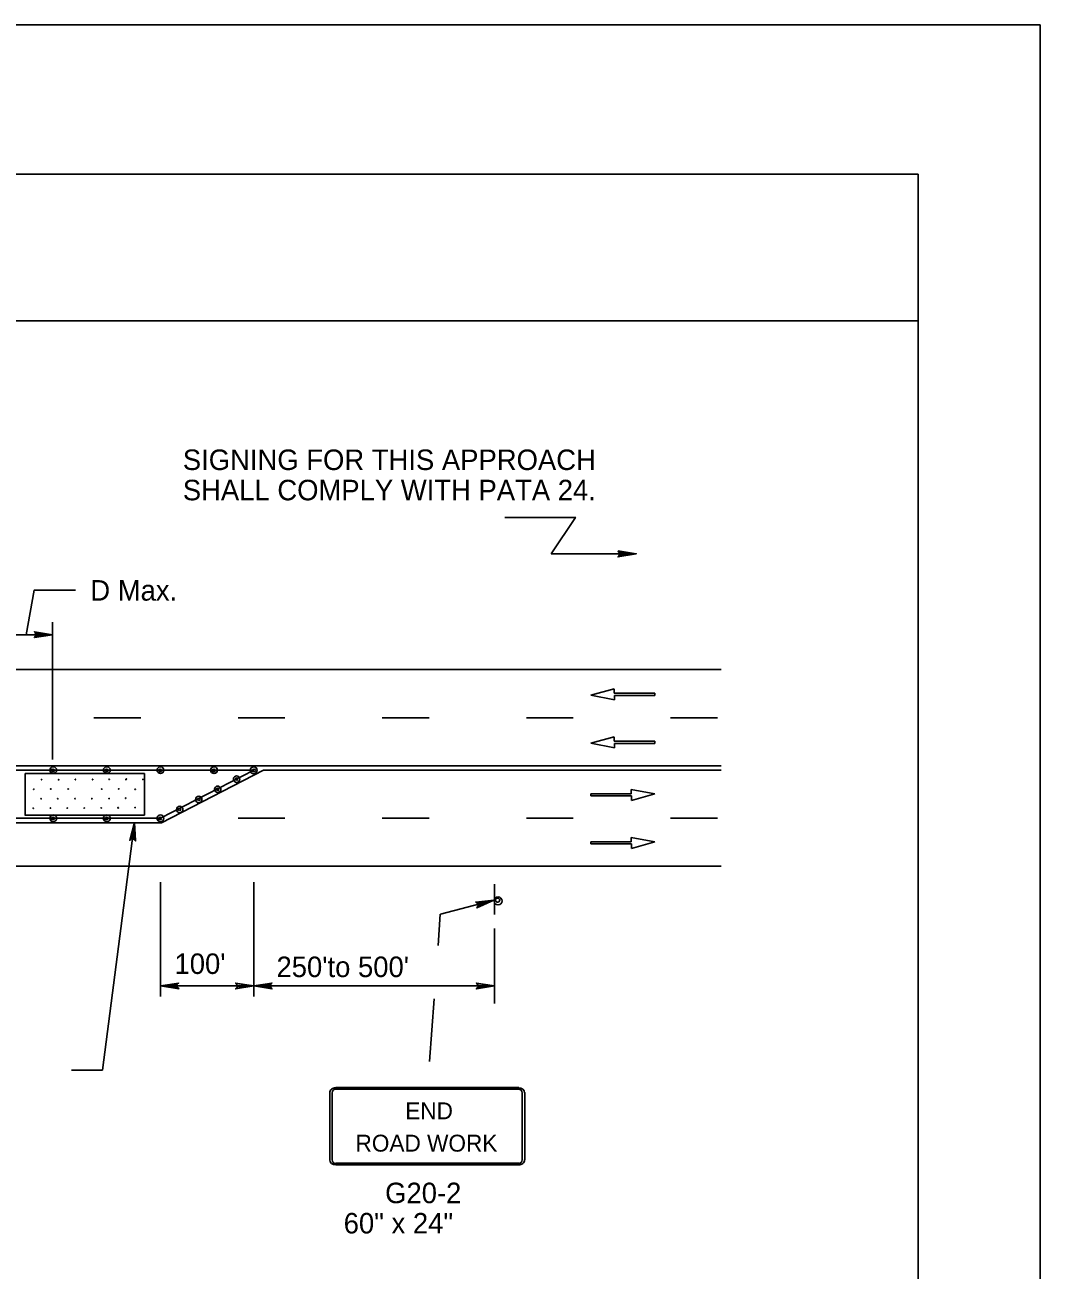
# Model space of a CAD drawing. Extents: x -14145 to -13521, y 30244 to 30661.
# Drawn here: x -13767.57 to -13757.17, y 30329.56 to 30342.31 of the extents above; entities that cross this region are included whole.
import ezdxf

# ---------------------------------------------------------------- set-up
doc = ezdxf.new("R2010")
doc.units = 0
for name, color, linetype in [('1', 7, 'Continuous'), ('10', 7, 'Continuous'), ('2', 7, 'Continuous'), ('61', 7, 'Continuous')]:
    doc.layers.add(name, color=color, linetype=linetype)

msp = doc.modelspace()

# ---------------------------------------------------------------- linework, layer by layer
at = {"layer": '1'}
for p, q in [((-13762.654, 30337.264), (-13761.928, 30337.264)), ((-13761.929, 30337.263), (-13762.18, 30336.89)), ((-13762.18, 30336.89), (-13761.309, 30336.89)), ((-13767.284, 30334.784), (-13767.284, 30336.19)), ((-13767.825, 30336.063), (-13767.283, 30336.063)), ((-13787.525, 30335.705), (-13760.437, 30335.705)), ((-13761.533, 30335.509), (-13761.774, 30335.443)), ((-13761.774, 30335.443), (-13761.53, 30335.397)), ((-13761.533, 30335.464), (-13761.533, 30335.509)), ((-13761.117, 30335.464), (-13761.533, 30335.464)), ((-13761.53, 30335.397), (-13761.53, 30335.442)), ((-13761.53, 30335.442), (-13761.117, 30335.442)), ((-13761.117, 30335.442), (-13761.117, 30335.464)), ((-13766.381, 30335.213), (-13766.861, 30335.213)), ((-13764.905, 30335.213), (-13765.385, 30335.213)), ((-13763.429, 30335.213), (-13763.909, 30335.213)), ((-13761.953, 30335.213), (-13762.433, 30335.213)), ((-13760.477, 30335.213), (-13760.957, 30335.213)), ((-13761.533, 30335.017), (-13761.774, 30334.951)), ((-13761.774, 30334.951), (-13761.53, 30334.905)), ((-13761.533, 30334.972), (-13761.533, 30335.017)), ((-13761.117, 30334.972), (-13761.533, 30334.972)), ((-13761.53, 30334.905), (-13761.53, 30334.95)), ((-13761.53, 30334.95), (-13761.117, 30334.95)), ((-13761.117, 30334.95), (-13761.117, 30334.972)), ((-13787.525, 30334.721), (-13760.437, 30334.721)), ((-13772.345, 30334.676), (-13765.224, 30334.676)), ((-13766.179, 30334.183), (-13765.224, 30334.675)), ((-13766.168, 30334.138), (-13765.125, 30334.676)), ((-13765.125, 30334.676), (-13760.438, 30334.676)), ((-13766.341, 30334.641), (-13767.565, 30334.641)), ((-13767.565, 30334.215), (-13767.565, 30334.641)), ((-13766.341, 30334.215), (-13766.341, 30334.641)), ((-13761.36, 30334.434), (-13761.774, 30334.434)), ((-13761.774, 30334.434), (-13761.774, 30334.412)), ((-13761.117, 30334.433), (-13761.36, 30334.479)), ((-13761.36, 30334.479), (-13761.36, 30334.434)), ((-13761.358, 30334.366), (-13761.117, 30334.433)), ((-13761.774, 30334.412), (-13761.358, 30334.412)), ((-13761.358, 30334.412), (-13761.358, 30334.366)), ((-13770.022, 30334.183), (-13766.179, 30334.183)), ((-13767.566, 30334.215), (-13766.342, 30334.215)), ((-13764.905, 30334.184), (-13765.385, 30334.184)), ((-13763.429, 30334.184), (-13763.909, 30334.184)), ((-13761.953, 30334.184), (-13762.433, 30334.184)), ((-13760.477, 30334.184), (-13760.957, 30334.184)), ((-13770.022, 30334.138), (-13766.168, 30334.138)), ((-13766.445, 30334.138), (-13766.773, 30331.604)), ((-13761.36, 30333.942), (-13761.774, 30333.942)), ((-13761.774, 30333.942), (-13761.774, 30333.92)), ((-13761.774, 30333.92), (-13761.358, 30333.92)), ((-13761.117, 30333.941), (-13761.36, 30333.987)), ((-13761.36, 30333.987), (-13761.36, 30333.942)), ((-13761.358, 30333.874), (-13761.117, 30333.941)), ((-13761.358, 30333.92), (-13761.358, 30333.874)), ((-13787.525, 30333.692), (-13760.437, 30333.692)), ((-13766.178, 30332.357), (-13766.178, 30333.529)), ((-13765.224, 30332.357), (-13765.224, 30333.529)), ((-13762.759, 30333.51), (-13762.759, 30333.198)), ((-13762.759, 30333.51), (-13762.759, 30333.198)), ((-13763.312, 30333.203), (-13762.765, 30333.343)), ((-13763.337, 30332.881), (-13763.314, 30333.203)), ((-13762.76, 30333.053), (-13762.76, 30332.285)), ((-13766.178, 30332.466), (-13765.224, 30332.466)), ((-13762.759, 30332.466), (-13765.224, 30332.466)), ((-13763.425, 30331.693), (-13763.377, 30332.336)), ((-13766.773, 30331.604), (-13767.09, 30331.604)), ((-13764.445, 30331.375), (-13764.445, 30330.687)), ((-13764.42, 30331.375), (-13764.42, 30330.687)), ((-13762.511, 30331.426), (-13764.384, 30331.426)), ((-13762.511, 30331.426), (-13764.384, 30331.426)), ((-13762.511, 30331.411), (-13764.384, 30331.411)), ((-13762.511, 30331.411), (-13764.384, 30331.411)), ((-13762.475, 30330.687), (-13762.475, 30331.375)), ((-13762.45, 30330.687), (-13762.45, 30331.375)), ((-13764.384, 30330.65), (-13762.511, 30330.65)), ((-13764.384, 30330.635), (-13762.511, 30330.635))]:
    msp.add_line(p, q, dxfattribs=at)
for points in [[(-13761.488, 30336.913), (-13761.48, 30336.899), (-13761.308, 30336.891), (-13761.488, 30336.913), (-13761.493, 30336.92), (-13761.308, 30336.891), (-13761.479, 30336.879), (-13761.487, 30336.869), (-13761.308, 30336.891), (-13761.496, 30336.859), (-13761.487, 30336.869)], [(-13767.049, 30336.519), (-13767.471, 30336.519), (-13767.554, 30336.063)], [(-13767.463, 30336.087), (-13767.457, 30336.075), (-13767.283, 30336.063), (-13767.463, 30336.087), (-13767.469, 30336.093), (-13767.283, 30336.063), (-13767.457, 30336.057), (-13767.463, 30336.045), (-13767.283, 30336.063), (-13767.469, 30336.033), (-13767.463, 30336.045)], [(-13766.487, 30333.969), (-13766.474, 30333.973), (-13766.444, 30334.139), (-13766.487, 30333.969), (-13766.494, 30333.957), (-13766.444, 30334.139), (-13766.457, 30333.971), (-13766.445, 30333.963), (-13766.444, 30334.139), (-13766.434, 30333.951), (-13766.445, 30333.963)], [(-13762.945, 30333.319), (-13762.933, 30333.307), (-13762.765, 30333.343), (-13762.945, 30333.319), (-13762.951, 30333.325), (-13762.765, 30333.343), (-13762.927, 30333.289), (-13762.933, 30333.277), (-13762.765, 30333.343), (-13762.939, 30333.265), (-13762.933, 30333.277)], [(-13765.998, 30332.448), (-13766.01, 30332.46), (-13766.178, 30332.466), (-13765.998, 30332.448), (-13765.992, 30332.436), (-13766.178, 30332.466), (-13766.01, 30332.478), (-13766.004, 30332.49), (-13766.178, 30332.466), (-13765.992, 30332.496), (-13766.004, 30332.49)], [(-13765.404, 30332.49), (-13765.392, 30332.472), (-13765.224, 30332.466), (-13765.404, 30332.49), (-13765.41, 30332.496), (-13765.224, 30332.466), (-13765.392, 30332.46), (-13765.398, 30332.442), (-13765.224, 30332.466), (-13765.41, 30332.436), (-13765.398, 30332.442)], [(-13765.044, 30332.448), (-13765.05, 30332.46), (-13765.224, 30332.466), (-13765.044, 30332.448), (-13765.038, 30332.436), (-13765.224, 30332.466), (-13765.05, 30332.478), (-13765.044, 30332.49), (-13765.224, 30332.466), (-13765.038, 30332.496), (-13765.044, 30332.49)], [(-13762.939, 30332.49), (-13762.927, 30332.472), (-13762.759, 30332.466), (-13762.939, 30332.49), (-13762.945, 30332.496), (-13762.759, 30332.466), (-13762.927, 30332.454), (-13762.939, 30332.442), (-13762.759, 30332.466), (-13762.945, 30332.436), (-13762.939, 30332.442)]]:
    msp.add_lwpolyline(points, dxfattribs=at)
for centre, radius in [((-13767.277, 30334.676), 0.0354), ((-13767.28, 30334.673), 0.0143), ((-13766.728, 30334.676), 0.0354), ((-13766.731, 30334.673), 0.0143), ((-13766.179, 30334.676), 0.0354), ((-13766.182, 30334.673), 0.0143), ((-13765.63, 30334.676), 0.0354), ((-13765.633, 30334.673), 0.0143), ((-13765.224, 30334.675), 0.0354), ((-13765.221, 30334.672), 0.0143), ((-13767.396, 30334.579), 0.00272), ((-13767.221, 30334.578), 0.00272), ((-13767.049, 30334.58), 0.00272), ((-13766.874, 30334.58), 0.00272), ((-13766.703, 30334.582), 0.00272), ((-13766.532, 30334.58), 0.00272), ((-13766.528, 30334.585), 0.00272), ((-13766.358, 30334.581), 0.00272), ((-13765.399, 30334.583), 0.0331), ((-13765.398, 30334.584), 0.012), ((-13767.476, 30334.481), 0.00272), ((-13767.301, 30334.483), 0.00272), ((-13767.123, 30334.483), 0.00272), ((-13766.78, 30334.482), 0.00272), ((-13766.606, 30334.484), 0.00272), ((-13766.438, 30334.481), 0.00272), ((-13765.593, 30334.48), 0.0331), ((-13765.592, 30334.481), 0.012), ((-13767.401, 30334.383), 0.00272), ((-13767.23, 30334.383), 0.00272), ((-13767.053, 30334.384), 0.00272), ((-13766.959, 30334.288), 0.00272), ((-13766.88, 30334.384), 0.00272), ((-13766.785, 30334.289), 0.00272), ((-13766.705, 30334.385), 0.00272), ((-13766.613, 30334.292), 0.00272), ((-13766.612, 30334.289), 0.00272), ((-13766.534, 30334.389), 0.00272), ((-13766.439, 30334.293), 0.00272), ((-13765.982, 30334.273), 0.0331), ((-13765.787, 30334.376), 0.0331), ((-13765.786, 30334.377), 0.012), ((-13767.481, 30334.286), 0.00272), ((-13767.277, 30334.183), 0.0354), ((-13767.306, 30334.287), 0.00272), ((-13767.28, 30334.18), 0.0143), ((-13767.133, 30334.287), 0.00272), ((-13766.728, 30334.183), 0.0354), ((-13766.731, 30334.18), 0.0143), ((-13766.179, 30334.183), 0.0354), ((-13766.182, 30334.18), 0.0143), ((-13765.981, 30334.274), 0.012), ((-13762.722, 30333.337), 0.0408)]:
    msp.add_circle(centre, radius, dxfattribs=at)
msp.add_arc((-13762.727, 30333.345), 0.0214, 189.521, 184.2501, dxfattribs=at)
for centre, major_axis, ratio, start_param, end_param in [((-13764.385, 30331.373), (0.0609, 0), 0.839899, 1.570796, 3.141593), ((-13764.385, 30331.373), (0, -0.0365), 0.999938, 3.141593, 4.712389), ((-13762.513, 30331.373), (-0.0609, 0), 0.839899, 3.141593, 4.712389), ((-13762.513, 30331.373), (0, 0.0365), 0.999938, 4.712389, 6.283185), ((-13764.385, 30330.685), (0.0609, 0), 0.839899, 3.141593, 4.712389), ((-13764.385, 30330.685), (0, -0.0365), 0.999938, 4.712389, 6.283185), ((-13762.513, 30330.685), (0, 0.0365), 0.999938, 3.141593, 4.712389), ((-13762.513, 30330.685), (-0.0609, 0), 0.839899, 1.570796, 3.141593)]:
    msp.add_ellipse(centre, major_axis=major_axis, ratio=ratio, start_param=start_param, end_param=end_param, dxfattribs=at)
at = {"layer": '10'}
for p, q in [((-13789.874, 30340.777), (-13758.422, 30340.777)), ((-13758.422, 30340.777), (-13758.422, 30318.207)), ((-13789.874, 30339.277), (-13758.422, 30339.277))]:
    msp.add_line(p, q, dxfattribs=at)
at = {"layer": '61'}
msp.add_lwpolyline([(-13790.174, 30342.307), (-13757.174, 30342.307), (-13757.174, 30316.807), (-13790.174, 30316.807)], close=True, dxfattribs=at)

# ---------------------------------------------------------------- texts
at = {"layer": '1'}
for s, p in [('END', (-13763.673, 30331.101)), ('ROAD WORK', (-13764.182, 30330.77))]:
    msp.add_text(s, height=0.173, dxfattribs=at).set_placement(p)
at = {"layer": '2'}
for s, p in [('SIGNING FOR THIS APPROACH ', (-13765.95, 30337.749)), ('SHALL COMPLY WITH PATA 24.', (-13765.95, 30337.439)), ('D Max.', (-13766.897, 30336.412)), ("100'", (-13766.035, 30332.589)), ("250'to 500'", (-13764.991, 30332.557)), ('G20-2', (-13763.879, 30330.242)), ('60" x 24"', (-13764.303, 30329.932))]:
    msp.add_text(s, height=0.21, dxfattribs=at).set_placement(p)

doc.saveas('drawing.dxf')
